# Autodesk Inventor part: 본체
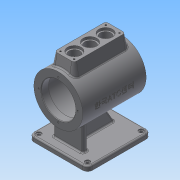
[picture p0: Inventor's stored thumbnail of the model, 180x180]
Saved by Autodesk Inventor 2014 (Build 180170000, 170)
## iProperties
Created: 2015-11
Part Number: 본체
Material: 알루미늄 6061
Document SubType Name: Modeling
Designer: mduedu
Density: 2.71 g/cm^3
Appearance: 기본값
Mass: 1557.05 g
Surface Area: 1415.52 cm^2
Volume: 574.557 cm^3
Author: mduedu
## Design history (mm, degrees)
sketch "스케치2"
  geometry: C1 r 50 at (0, 0); 1 further point
  constraints: 1 centre point, 1 coincident
  dimensions: "d147" = 100 diameter of C1
extrude "돌출1" new body sketch "스케치2" stored distance "d12" = 130; taper "d13" = 0 deg
feature "쉘1" dims "d31" = 15, "d32" = 6, "d33" = 15
sketch "스케치5"
  geometry: C1 r 35 at (0, 0); 1 further point
  constraints: 1 centre point, 1 coincident
  dimensions: "d34" = 70 diameter of C1
extrude "돌출3" cut sketch "스케치5" stored distance "d36" = 3; taper "d37" = 0 deg
node "작업 평면1"
sketch "스케치6"
  geometry: L1 (-65, -60)-(65, -60); L2 (65, -60)-(65, 60); L3 (65, 60)-(-65, 60); L4 (-65, 60)-(-65, -60); L5 (-65, -60)-(65, 60); L6 (65, -60)-(-65, 60); 1 further point
  constraints: 12 end point, 2 midpoint, 2 parallel, 1 horizontal, 1 perpendicular
  dimensions: "d41" = 120 distance of L3.end L1.start; "d43" = 130 distance of L2.end L3.end
extrude "돌출4" join sketch "스케치6" distance "d44" = 10; taper "d45" = 0 deg
sketch "스케치19"
  geometry: L1 (-45, 30)-(-35, 30); L2 (-35, 30)-(-35, -30); L3 (-35, -30)-(-45, -30); L4 (-45, -30)-(-45, 30); L5 (-65, 60)-(-65, -60) reference; 2 further points
  constraints: 8 end point, 2 parallel, 1 horizontal, 1 horizontal alignment, 1 midpoint, 1 perpendicular
  dimensions: "d150" = 20 distance between parallel lines of L4 L5; "d151" = 10 distance of L1.start L1.end; "d152" = 60 distance of L3.end L1.start
extrude "돌출9" join sketch "스케치19" stored distance "d153" = 10; taper "d154" = 0 deg
sketch "스케치20"
  geometry: L1 (65, 35)-(50, 35) reference; L2 (50, 35)-(50, 44) reference; L3 (50, 44)-(-50, 44) reference; L4 (-50, 44)-(-50, 35) reference; L5 (-50, 35)-(-65, 35) reference; L6 (-65, 35)-(-65, 50) reference; L7 (-65, 50)-(65, 50) reference; L8 (65, 50)-(65, 35) reference; L9 (50, -35)-(65, -35) reference; L10 (65, -35)-(65, -50) reference; L11 (65, -50)-(45, -50) reference; L12 (45, -50)-(45, -90) reference; L13 (45, -90)-(65, -90) reference; L14 (65, -90)-(65, -100) reference; L15 (65, -100)-(-65, -100) reference; L16 (-65, -100)-(-65, -90) reference; L17 (-65, -90)-(35, -90) reference; L18 (35, -90)-(35, -50) reference; L19 (35, -50)-(-65, -50) reference; L20 (-65, -50)-(-65, -35) reference; L21 (-65, -35)-(-50, -35) reference; L22 (-50, -35)-(-50, -44) reference; L23 (-50, -44)-(50, -44) reference; L24 (50, -44)-(50, -35) reference; L25 (-45, -90)-(-21.906, -50); 1 further point
  constraints: 2 end point, 2 point on line
  dimensions: "d155" = 20 distance from line of L25.start L16; "d156" = 120 deg angle of L25 L17
feature "리브2" sketch "스케치20" dims "d157" = 1, "d158" = 10, "d159" = 0, "d160" = 0, "d161" = 1, "d162" = 1
fillet "모깎기21" dims "d163" = 3
fillet "모깎기22" dims "d164" = 3
fillet "모깎기23" dims "d165" = 3
sketch "스케치21" dims "d166" = 80
  geometry: 3 further points
  constraints: 2 horizontal alignment, 1 coincident, 2 other
hole "구멍6" sketch "스케치21" at (40, 0) diameter "d168" = 3.242; stored, may be unused: countersink angle "d172" = 90 deg, drill point angle "d174" = 118 deg; dims "d169" = 9, "d170" = 4, "d171" = 2, "d173" = 11
node "작업 평면2"
sketch "스케치13"
  geometry: L1 (-52.5, -20)-(52.5, -20); L2 (52.5, -20)-(52.5, 20); L3 (52.5, 20)-(-52.5, 20); L4 (-52.5, 20)-(-52.5, -20); L5 (-52.5, -20)-(52.5, 20); L6 (52.5, -20)-(-52.5, 20); 1 further point
  constraints: 12 end point, 2 midpoint, 2 parallel, 1 horizontal, 1 perpendicular
  dimensions: "d93" = 105 distance of L2.end L3.end; "d95" = 40 distance of L1.end L2.end
extrude "돌출8" join sketch "스케치13" stored distance "d96" = 80; taper "d97" = 0 deg
fillet "모깎기15" dims "d98" = 5
feature "면 기울기1" dims angle "d178" = 10 deg
fillet "모깎기24" dims "d179" = 3
sketch "스케치14"
  geometry: L1 (-52.5, 15)-(-52.5, -15) reference; L2 (52.5, -15)-(52.5, 15) reference; L3 (-52.5, 0)-(52.5, 0); 4 further points
  constraints: 2 end point, 2 midpoint, 2 point on line, 1 coincident
  dimensions: "d100" = 32 distance of point (-32, 0) point (0, 0); "d102" = 32 distance of point (32, 0) point (0, 0) (derived)
hole "구멍3" sketch "스케치14" at (-32, 0), (0, 0), (32, 0) diameter "d103" = 22; stored, may be unused: countersink angle "d107" = 90 deg, drill point angle "d109" = 118 deg; dims "d104" = 8, "d105" = 28, "d106" = 5, "d108" = 10
sketch "스케치15"
  geometry: L1 (46.5, -14)-(-46.5, -14); L2 (-46.5, -14)-(-46.5, 14); L3 (-46.5, 14)-(46.5, 14); L4 (46.5, 14)-(46.5, -14); L5 (46.5, -14)-(-46.5, 14); L6 (-46.5, -14)-(46.5, 14); L7 (47.5, 20)-(-47.5, 20) reference; L8 (-52.5, 15)-(-52.5, -15) reference; 5 further points
  constraints: 12 end point, 4 coincident, 2 midpoint, 2 parallel, 1 horizontal, 1 perpendicular
  dimensions: "d110" = 6 distance between parallel lines of L3 L7; "d111" = 6 distance between parallel lines of L2 L8
hole "구멍4" sketch "스케치15" at (-46.5, 14), (46.5, 14), (46.5, -14), (-46.5, -14) diameter "d112" = 3.242; stored, may be unused: countersink angle "d116" = 90 deg, drill point angle "d118" = 118 deg; dims "d113" = 10, "d114" = 28, "d115" = 5, "d117" = 13
node "작업 평면3"
sketch "스케치22"
  geometry: 2 further points
  constraints: 1 coincident, 1 other
feature "엠보싱3" sketch "스케치22" dims "d32" = 6, "d181" = 0.5, "d182" = 0
chamfer "모따기2" distance "d183" = 1; stored, may be unused: second distance "d184" = 2, angle "d185" = 45 deg
fillet "모깎기25" dims "d186" = 10
sketch "스케치23"
  geometry: L1 (55, 60)-(-55, 60) reference; L2 (65, -50)-(65, 50) reference; L3 (-55, -60)-(55, -60) reference; L4 (-65, 50)-(-65, -50) reference; A1 r 10 centre (-55, 50) between (-55, 60) and (-65, 50) reference; A2 r 10 centre (55, 50) between (65, 50) and (55, 60) reference; A3 r 10 centre (55, -50) between (55, -60) and (65, -50) reference; A4 r 10 centre (-55, -50) between (-65, -50) and (-55, -60) reference; 1 further point
hole "구멍7" sketch "스케치23" at (-55, 50), (-55, -50), (55, -50), (55, 50) diameter "d187" = 6; stored, may be unused: countersink angle "d191" = 90 deg, drill point angle "d193" = 118 deg; dims "d188" = 9, "d189" = 10, "d190" = 2, "d192" = 11
fillet "모깎기26" dims "d194" = 3
node "솔리드1"
pattern_circular "원형 패턴2" dims angle "d176" = 360 deg
mirror "대칭5"
node "투영된 루프2"
node "절단 모서리 투영1"
